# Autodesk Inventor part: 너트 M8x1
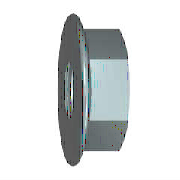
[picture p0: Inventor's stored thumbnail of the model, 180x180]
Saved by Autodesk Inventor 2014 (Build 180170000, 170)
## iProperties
Created: 2015-12
Part Number: 너트 M8x1
Material: 스테인리스강
Description: 플랜지붙이 6각 너트 - 일반 스레드
Document SubType Name: Modeling
Standard: ISO 4161
Designer: mdu
Standard Revision: 2판 1999-03-15
Standards Organization: ISO
Language: ko-KR
Size Designation: M8
Categories: <MemberInstance><Categories><Category DisplayName="조임쇠" InternalName="e4da775c-781d-43d5-af7c-5136215cf5a6" Mnemonic="FSTN"><Category DisplayName="너트" InternalN
Density: 8.08 g/cm^3
Appearance: 노란색
Mass: 8.84458 g
Surface Area: 8.9064 cm^2
Volume: 1.09463 cm^3
Author: mdu
IsCustomPart: 1
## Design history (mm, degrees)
sketch "스케치1"
  geometry: L1 (-1.844, 0)-(9.641, 0) reference; L2 (3.107, 6.5)-(2.288, 8.257); L3 (3.107, 6.5)-(8, 6.5); L4 (8, 6.5)-(8, 0); L5 (3.107, 6.5)-(3.107, 0); L6 (0, -1.835)-(0, 11.01) reference; A1 r 1.2 centre (1.2, 7.75) between (2.288, 8.257) and (0, 7.75); 1 further point
  constraints: 8 end point, 3 point on line, 2 perpendicular, 2 point on circle, 2 tangent, 1 centre point, 1 parallel
  dimensions: "d2" = 13 diameter of L3 L1 (= SW); "d4" = 17.9 dimension on A1 L1 (= LADI); "d5" = 1.2 radius of A1 (= PHH); "d15" = 8 distance between parallel lines of L4 L6 (= KOH); "d16" = 25 deg angle of L6 L2 (= KEWI)
revolve "링" sketch "스케치1" stored, may be unused: angle "d8" = 90 deg
sketch "스케치2"
  geometry: L1 (-6.5, -3.753)-(-6.5, 3.753); L2 (-6.5, 3.753)-(0, 7.506); L3 (0, 7.506)-(6.5, 3.753); L4 (6.5, 3.753)-(6.5, -3.753); L5 (6.5, -3.753)-(0, -7.506); L6 (0, -7.506)-(-6.5, -3.753); C1 r 4.9 at (0, 0); C2 r 7.75 at (0, 0) reference; 1 further point
  constraints: 12 end point, 1 centre point, 1 coincident, 1 vertical, 11 other
  dimensions: "d6" = 15.01111 distance of L5.end L2.end (= 1.1547 x SW)
extrude "본체" join sketch "스케치2" distance "d7" = 8 (= KOH); taper "d9" = 0 deg
sketch "스케치3"
  geometry: L1 (2.638, 7.506)-(8, 7.506) reference; L2 (8, 3.753)-(8, 7.506) reference; L3 (0, -7.75)-(0, 7.75) reference; L4 (-1.6, 0)-(9.6, 0) reference; L5 (7.419, 7.506)-(8, 6.5)
  constraints: 2 end point, 2 point on line
  dimensions: "d10" = 30 deg angle of L2 L5 (= ANG1); "d11" = 13 diameter of L5.end L4 (= SW0)
revolve "모따기1" sketch "스케치3" stored, may be unused: angle "d24" = 90 deg
sketch "스케치4"
  geometry: C1 r 7.75 at (0, 0) reference; 1 further point
  constraints: 1 coincident
hole "스레드" sketch "스케치4" at (0, 0) diameter "d25" = 6.917; stored, may be unused: countersink angle "d29" = 82 deg, drill point angle "d31" = 118 deg; dims "d26" = 6, "d27" = 4, "d28" = 2, "d30" = 8
workaxis "Work Axis1"
workplane "Work Plane1"
body "Solid1"
chamfer "모따기2" distance "d12" = 0.67658 (= -0.5 x GD1 + 0.5 x NND); stored, may be unused: angle "d13" = 30 deg, second distance "d46" = 0.67658 (= -0.5 x GD1 + 0.5 x NND)
chamfer "모따기3" distance "d51" = 0.67658 (= -0.5 x GD1 + 0.5 x NND); stored, may be unused: second distance "d52" = 2, angle "d53" = 45 deg
other parameters: "ANG1" = 30 deg [user parameter; used in 1 equation term], "KEWI" = 25 deg [user parameter; used in 1 equation term], "NND" = 8 [user parameter; used in 4 equation terms], "LADI" = 17.9 [user parameter; used in 2 equation terms], "SW" = 13 [user parameter; used in 3 equation terms], "PHH" = 1.2 [user parameter; used in 3 equation terms], "KOH" = 8 (= NND) [user parameter; used in 2 equation terms], "SW0" = 13 [user parameter; used in 1 equation term], "GD1" = 6.64684 (computed from THREADDIA, PTC, TOA) [user parameter; used in 3 equation terms], "d1" = 17.9 (= LADI), "d3" = 1.2 (= PHH), "d45" = 0, "d47" = 0, "d49" = 0, "d54" = 0, "GUL" = 0.67658 (= 0.541266 x PTC) [user parameter], "TPU" = 8 (computed from PTC) [user parameter], "RR" = 1.2 (= PHH) [user parameter], "THREADDIA" = 8 [user parameter; used in 1 equation term], "TOA" = 30 deg [user parameter; used in 1 equation term], "PTC" = 1.25 [user parameter; used in 4 equation terms], "GAL" = 0.67658 (= 0.541266 x PTC) [user parameter], "E0" = 15.015 (= 1.155 x SW) [user parameter]
